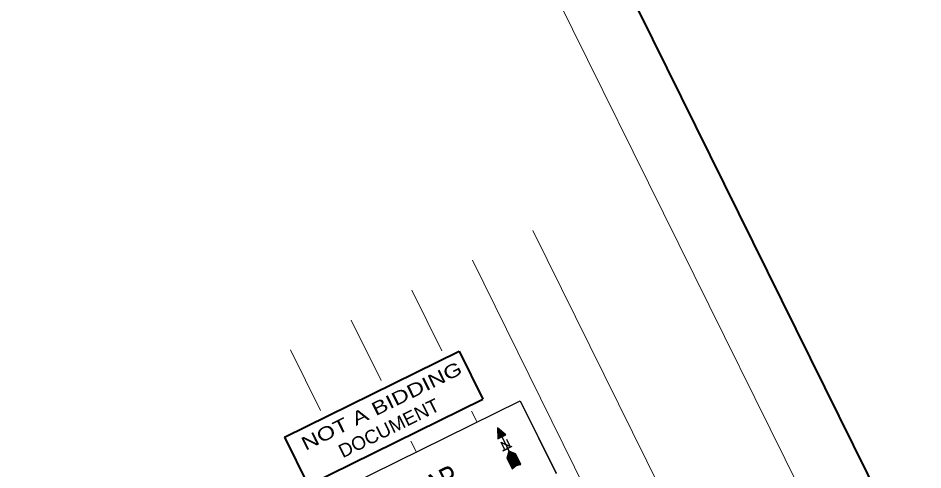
# Model space of a CAD drawing. Extents: x 2356606 to 2371222, y 6973096 to 6982644.
# Drawn here: x 2356606 to 2357945, y 6974009 to 6974679 of the extents above; entities that cross this region are included whole.
import ezdxf
from ezdxf.enums import TextEntityAlignment as Align

# ---------------------------------------------------------------- set-up
doc = ezdxf.new("R2010")
doc.units = 0
doc.header["$LTSCALE"] = 2
for name, color, linetype, lineweight in [('44', 7, 'Continuous', 13), ('62', 7, 'Continuous', 13), ('63', 7, 'Continuous', 13)]:
    doc.layers.add(name, color=color, linetype=linetype, lineweight=lineweight)

msp = doc.modelspace()

# ---------------------------------------------------------------- linework, layer by layer
at = {"layer": '44'}
msp.add_line((2358199.427, 6973096.266), (2356606.11, 6976324.656), dxfattribs=at)
at = {"layer": '44', "lineweight": 40}
msp.add_lwpolyline([(2358244.847, 6973230.201), (2356740.046, 6976279.238), (2369364.897, 6982510.022)], dxfattribs=at)
at = {"layer": '62'}
for p, q in [((2357367.886, 6974364.182), (2357723.359, 6973643.92)), ((2357278.212, 6974319.925), (2357633.685, 6973599.663)), ((2357277.056, 6974096.314), (2357285.076, 6974080.064)), ((2357315.643, 6974070.883), (2357316.066, 6974071.091)), ((2357321.745, 6974058.111), (2357315.651, 6974070.459)), ((2357315.66, 6974070.189), (2357316.587, 6974070.646)), ((2357315.665, 6974069.515), (2357317.118, 6974070.23)), ((2357321.182, 6974057.833), (2357315.684, 6974068.97)), ((2357315.692, 6974068.799), (2357317.65, 6974069.767)), ((2357315.698, 6974068.124), (2357318.16, 6974069.339)), ((2357315.734, 6974067.441), (2357318.682, 6974068.896)), ((2357320.613, 6974057.554), (2357315.734, 6974067.441)), ((2357315.761, 6974066.725), (2357319.211, 6974068.43)), ((2357320.048, 6974057.275), (2357315.767, 6974065.95)), ((2357315.768, 6974066.051), (2357319.722, 6974068.005)), ((2357315.783, 6974065.358), (2357320.265, 6974067.57)), ((2357315.8, 6974064.662), (2357320.785, 6974067.124)), ((2357319.484, 6974056.995), (2357315.809, 6974064.441)), ((2357315.817, 6974063.968), (2357321.326, 6974066.689)), ((2357315.853, 6974063.285), (2357321.847, 6974066.243)), ((2357318.919, 6974056.716), (2357315.861, 6974062.912)), ((2357315.87, 6974062.591), (2357322.388, 6974065.807)), ((2357315.887, 6974061.897), (2357322.909, 6974065.362)), ((2357318.354, 6974056.438), (2357315.894, 6974061.423)), ((2357315.92, 6974060.506), (2357323.951, 6974064.471)), ((2357315.922, 6974061.211), (2357323.43, 6974064.916)), ((2357315.937, 6974059.811), (2357324.471, 6974064.026)), ((2357317.79, 6974056.161), (2357315.946, 6974059.893)), ((2357315.974, 6974059.127), (2357325.013, 6974063.588)), ((2357317.224, 6974055.881), (2357315.981, 6974058.403)), ((2357315.988, 6974058.434), (2357325.534, 6974063.143)), ((2357315.997, 6974057.76), (2357326.046, 6974062.72)), ((2357322.31, 6974058.39), (2357316.017, 6974071.142)), ((2357316.042, 6974057.055), (2357326.596, 6974062.264)), ((2357316.06, 6974056.359), (2357327.117, 6974061.819)), ((2357316.067, 6974055.685), (2357327.629, 6974061.393)), ((2357322.874, 6974058.672), (2357317.219, 6974070.129)), ((2357323.42, 6974058.938), (2357318.401, 6974069.108)), ((2357324.005, 6974059.228), (2357319.613, 6974068.126)), ((2357324.57, 6974059.506), (2357320.815, 6974067.113)), ((2357325.114, 6974059.774), (2357321.988, 6974066.112)), ((2357325.7, 6974060.063), (2357323.211, 6974065.107)), ((2357326.245, 6974060.333), (2357324.392, 6974064.087)), ((2357326.81, 6974060.612), (2357325.585, 6974063.094)), ((2357327.394, 6974060.9), (2357326.807, 6974062.091)), ((2357187.382, 6974052.057), (2357195.402, 6974035.807)), ((2357316.659, 6974055.602), (2357316.034, 6974056.873)), ((2357316.113, 6974055.333), (2357316.083, 6974055.394)), ((2357329.561, 6974026.562), (2357342.335, 6974032.868)), ((2357329.586, 6974027.276), (2357341.772, 6974033.292)), ((2357329.8, 6974028.062), (2357340.997, 6974033.588)), ((2357329.839, 6974025.998), (2357342.614, 6974032.303)), ((2357330.035, 6974028.905), (2357340.226, 6974033.935)), ((2357330.118, 6974025.433), (2357342.891, 6974031.737)), ((2357330.26, 6974029.719), (2357339.443, 6974034.251)), ((2357330.517, 6974030.523), (2357338.671, 6974034.545)), ((2357330.732, 6974031.357), (2357337.898, 6974034.891)), ((2357339.716, 6974013.153), (2357330.732, 6974031.357)), ((2357330.97, 6974032.15), (2357337.122, 6974035.189)), ((2357340.211, 6974013.574), (2357330.988, 6974032.262)), ((2357331.194, 6974032.965), (2357336.339, 6974035.505)), ((2357340.706, 6974013.994), (2357331.245, 6974033.165)), ((2357331.43, 6974033.807), (2357335.567, 6974035.85)), ((2357341.204, 6974014.415), (2357331.501, 6974034.069)), ((2357331.667, 6974034.601), (2357334.794, 6974036.147)), ((2357341.696, 6974014.835), (2357331.755, 6974034.973)), ((2357331.891, 6974035.417), (2357334.031, 6974036.471)), ((2357342.206, 6974015.236), (2357332.017, 6974035.881)), ((2357332.119, 6974036.23), (2357333.248, 6974036.789)), ((2357342.699, 6974015.655), (2357332.272, 6974036.783)), ((2357343.273, 6974015.915), (2357332.896, 6974036.941)), ((2357343.898, 6974016.072), (2357333.781, 6974036.573)), ((2357344.504, 6974016.219), (2357334.644, 6974036.198)), ((2357345.16, 6974016.368), (2357335.537, 6974035.86)), ((2357345.774, 6974016.547), (2357336.421, 6974035.494)), ((2357346.388, 6974016.672), (2357337.274, 6974035.138)), ((2357347.03, 6974016.841), (2357338.178, 6974034.781)), ((2357347.637, 6974016.989), (2357339.042, 6974034.404)), ((2357348.261, 6974017.148), (2357339.925, 6974034.037)), ((2357348.906, 6974017.314), (2357340.829, 6974033.68)), ((2357349.51, 6974017.463), (2357341.682, 6974033.324)), ((2357337.231, 6974011.076), (2357329.451, 6974026.835)), ((2357337.745, 6974011.503), (2357329.727, 6974027.749)), ((2357338.222, 6974011.916), (2357329.964, 6974028.643)), ((2357338.716, 6974012.334), (2357330.218, 6974029.547)), ((2357330.398, 6974024.866), (2357343.171, 6974031.171)), ((2357339.211, 6974012.754), (2357330.477, 6974030.451)), ((2357330.677, 6974024.302), (2357343.45, 6974030.605)), ((2357330.956, 6974023.735), (2357343.731, 6974030.041)), ((2357331.235, 6974023.17), (2357344.008, 6974029.475)), ((2357331.514, 6974022.606), (2357344.287, 6974028.909)), ((2357331.791, 6974022.04), (2357344.566, 6974028.345)), ((2357332.07, 6974021.474), (2357344.843, 6974027.779)), ((2357332.352, 6974020.912), (2357345.124, 6974027.214)), ((2357332.621, 6974020.368), (2357345.393, 6974026.669)), ((2357332.908, 6974019.781), (2357345.683, 6974026.086)), ((2357333.187, 6974019.216), (2357345.96, 6974025.52)), ((2357333.458, 6974018.671), (2357346.23, 6974024.977)), ((2357333.744, 6974018.087), (2357346.517, 6974024.39)), ((2357334.013, 6974017.542), (2357346.788, 6974023.847)), ((2357334.293, 6974016.975), (2357347.065, 6974023.281)), ((2357334.581, 6974016.392), (2357347.354, 6974022.696)), ((2357334.849, 6974015.847), (2357347.622, 6974022.151)), ((2357335.129, 6974015.281), (2357347.901, 6974021.586)), ((2357335.409, 6974014.718), (2357348.181, 6974021.02)), ((2357335.686, 6974014.153), (2357348.461, 6974020.457)), ((2357335.965, 6974013.586), (2357348.738, 6974019.892)), ((2357336.244, 6974013.021), (2357349.016, 6974019.327)), ((2357343.766, 6974016.033), (2357349.295, 6974018.762)), ((2357346.649, 6974016.753), (2357349.577, 6974018.196)), ((2357336.52, 6974012.457), (2357342.254, 6974015.287)), ((2357336.802, 6974011.891), (2357340.211, 6974013.574)), ((2357337.082, 6974011.329), (2357338.169, 6974011.863)), ((2357349.489, 6974017.452), (2357349.854, 6974017.63))]:
    msp.add_line(p, q, dxfattribs=at)
at = {"layer": '62', "lineweight": 40}
for p, q in [((2357000.317, 6974057.993), (2357258.555, 6974185.442)), ((2357258.555, 6974185.442), (2357293.714, 6974114.204))]:
    msp.add_line(p, q, dxfattribs=at)
at = {"layer": '62', "lineweight": 25}
for p, q in [((2357315.488, 6974071.658), (2357343.151, 6974015.602)), ((2357323.572, 6974037.933), (2357336.973, 6974044.547))]:
    msp.add_line(p, q, dxfattribs=at)
at = {"layer": '62', "lineweight": 40}
msp.add_lwpolyline([(2357000.317, 6974057.993), (2357035.475, 6973986.756), (2357293.714, 6974114.204)], dxfattribs=at)
at = {"layer": '62', "lineweight": 25}
for points in [[(2356999.05, 6973805.301), (2356946.031, 6973912.733), (2357348.892, 6974111.56), (2357402.214, 6974004.278)], [(2357315.613, 6974071.396), (2357316.074, 6974055.313), (2357327.918, 6974061.159), (2357315.555, 6974071.517)], [(2357325.749, 6974040.388), (2357320.88, 6974050.254), (2357334.12, 6974044.069), (2357329.071, 6974054.299)], [(2357332.354, 6974037.024), (2357329.442, 6974026.804), (2357337.21, 6974011.065), (2357342.891, 6974015.826), (2357349.895, 6974017.552), (2357342.215, 6974033.108), (2357332.554, 6974037.074)]]:
    msp.add_lwpolyline(points, dxfattribs=at)
at = {"layer": '63'}
for p, q in [((2357188.539, 6974275.669), (2357232.797, 6974185.992)), ((2357098.865, 6974231.412), (2357143.123, 6974141.735)), ((2357009.192, 6974187.155), (2357053.45, 6974097.479)), ((2357277.056, 6974096.314), (2357285.076, 6974080.064)), ((2357315.513, 6974071.146), (2357315.936, 6974071.354)), ((2357321.615, 6974058.374), (2357315.521, 6974070.722)), ((2357315.53, 6974070.452), (2357316.457, 6974070.909)), ((2357315.535, 6974069.778), (2357316.988, 6974070.493)), ((2357321.052, 6974058.096), (2357315.554, 6974069.233)), ((2357315.562, 6974069.062), (2357317.52, 6974070.03)), ((2357315.568, 6974068.387), (2357318.03, 6974069.602)), ((2357315.604, 6974067.704), (2357318.552, 6974069.159)), ((2357320.483, 6974057.817), (2357315.604, 6974067.704)), ((2357315.631, 6974066.988), (2357319.081, 6974068.693)), ((2357319.918, 6974057.538), (2357315.637, 6974066.213)), ((2357315.638, 6974066.314), (2357319.592, 6974068.268)), ((2357315.653, 6974065.621), (2357320.135, 6974067.833)), ((2357315.67, 6974064.925), (2357320.655, 6974067.387)), ((2357319.354, 6974057.258), (2357315.679, 6974064.704)), ((2357315.687, 6974064.231), (2357321.196, 6974066.952)), ((2357315.723, 6974063.548), (2357321.717, 6974066.506)), ((2357318.789, 6974056.979), (2357315.731, 6974063.175)), ((2357315.74, 6974062.854), (2357322.258, 6974066.07)), ((2357315.757, 6974062.16), (2357322.779, 6974065.625)), ((2357318.224, 6974056.701), (2357315.764, 6974061.686)), ((2357315.79, 6974060.769), (2357323.821, 6974064.734)), ((2357315.792, 6974061.474), (2357323.3, 6974065.179)), ((2357315.807, 6974060.074), (2357324.341, 6974064.289)), ((2357317.66, 6974056.424), (2357315.816, 6974060.156)), ((2357315.844, 6974059.39), (2357324.883, 6974063.851)), ((2357317.094, 6974056.144), (2357315.851, 6974058.666)), ((2357315.858, 6974058.697), (2357325.404, 6974063.406)), ((2357315.867, 6974058.023), (2357325.916, 6974062.983)), ((2357322.18, 6974058.653), (2357315.887, 6974071.405)), ((2357315.912, 6974057.318), (2357326.466, 6974062.527)), ((2357315.93, 6974056.622), (2357326.987, 6974062.082)), ((2357315.937, 6974055.948), (2357327.499, 6974061.656)), ((2357322.744, 6974058.935), (2357317.089, 6974070.392)), ((2357323.29, 6974059.201), (2357318.271, 6974069.371)), ((2357323.875, 6974059.491), (2357319.483, 6974068.389)), ((2357324.44, 6974059.769), (2357320.685, 6974067.376)), ((2357324.984, 6974060.037), (2357321.858, 6974066.375)), ((2357325.57, 6974060.326), (2357323.081, 6974065.37)), ((2357326.115, 6974060.596), (2357324.262, 6974064.35)), ((2357326.68, 6974060.875), (2357325.455, 6974063.357)), ((2357327.264, 6974061.163), (2357326.677, 6974062.354)), ((2357187.382, 6974052.057), (2357195.402, 6974035.807)), ((2357316.529, 6974055.865), (2357315.904, 6974057.136)), ((2357315.983, 6974055.596), (2357315.953, 6974055.657)), ((2357329.431, 6974026.825), (2357342.205, 6974033.131)), ((2357329.456, 6974027.539), (2357341.642, 6974033.555)), ((2357329.67, 6974028.325), (2357340.867, 6974033.851)), ((2357329.709, 6974026.261), (2357342.484, 6974032.566)), ((2357329.905, 6974029.168), (2357340.096, 6974034.198)), ((2357329.988, 6974025.696), (2357342.761, 6974032)), ((2357330.13, 6974029.982), (2357339.313, 6974034.514)), ((2357330.268, 6974025.129), (2357343.041, 6974031.434)), ((2357330.387, 6974030.786), (2357338.541, 6974034.808)), ((2357330.602, 6974031.62), (2357337.768, 6974035.154)), ((2357339.586, 6974013.416), (2357330.602, 6974031.62)), ((2357330.84, 6974032.413), (2357336.992, 6974035.452)), ((2357340.081, 6974013.837), (2357330.858, 6974032.525)), ((2357331.064, 6974033.228), (2357336.209, 6974035.768)), ((2357340.576, 6974014.257), (2357331.115, 6974033.428)), ((2357331.3, 6974034.07), (2357335.437, 6974036.113)), ((2357341.074, 6974014.678), (2357331.371, 6974034.332)), ((2357331.537, 6974034.864), (2357334.664, 6974036.41)), ((2357341.566, 6974015.098), (2357331.625, 6974035.236)), ((2357331.761, 6974035.68), (2357333.901, 6974036.734)), ((2357342.076, 6974015.499), (2357331.887, 6974036.144)), ((2357331.989, 6974036.493), (2357333.118, 6974037.052)), ((2357342.569, 6974015.918), (2357332.142, 6974037.046)), ((2357343.143, 6974016.178), (2357332.766, 6974037.204)), ((2357343.768, 6974016.335), (2357333.651, 6974036.836)), ((2357344.374, 6974016.482), (2357334.514, 6974036.461)), ((2357345.03, 6974016.631), (2357335.407, 6974036.123)), ((2357345.644, 6974016.81), (2357336.291, 6974035.757)), ((2357346.258, 6974016.935), (2357337.144, 6974035.401)), ((2357346.9, 6974017.104), (2357338.048, 6974035.044)), ((2357347.507, 6974017.252), (2357338.912, 6974034.667)), ((2357348.131, 6974017.411), (2357339.795, 6974034.3)), ((2357348.776, 6974017.577), (2357340.699, 6974033.943)), ((2357349.38, 6974017.726), (2357341.552, 6974033.587)), ((2357337.101, 6974011.339), (2357329.321, 6974027.098)), ((2357337.615, 6974011.766), (2357329.597, 6974028.012)), ((2357338.092, 6974012.179), (2357329.834, 6974028.906)), ((2357338.586, 6974012.597), (2357330.088, 6974029.81)), ((2357339.081, 6974013.017), (2357330.347, 6974030.714)), ((2357330.547, 6974024.565), (2357343.32, 6974030.868)), ((2357330.826, 6974023.998), (2357343.601, 6974030.304)), ((2357331.105, 6974023.433), (2357343.878, 6974029.738)), ((2357331.384, 6974022.869), (2357344.157, 6974029.172)), ((2357331.661, 6974022.303), (2357344.436, 6974028.608)), ((2357331.94, 6974021.737), (2357344.713, 6974028.042)), ((2357332.222, 6974021.175), (2357344.994, 6974027.477)), ((2357332.491, 6974020.631), (2357345.263, 6974026.932)), ((2357332.778, 6974020.044), (2357345.553, 6974026.349)), ((2357333.057, 6974019.479), (2357345.83, 6974025.783)), ((2357333.328, 6974018.934), (2357346.1, 6974025.24)), ((2357333.614, 6974018.35), (2357346.387, 6974024.653)), ((2357333.883, 6974017.805), (2357346.658, 6974024.11)), ((2357334.163, 6974017.238), (2357346.935, 6974023.544)), ((2357334.451, 6974016.655), (2357347.224, 6974022.959)), ((2357334.719, 6974016.11), (2357347.492, 6974022.414)), ((2357334.999, 6974015.544), (2357347.771, 6974021.849)), ((2357335.279, 6974014.981), (2357348.051, 6974021.283)), ((2357335.556, 6974014.416), (2357348.331, 6974020.72)), ((2357335.835, 6974013.849), (2357348.608, 6974020.155)), ((2357336.114, 6974013.284), (2357348.886, 6974019.59)), ((2357343.636, 6974016.296), (2357349.165, 6974019.025)), ((2357346.519, 6974017.016), (2357349.447, 6974018.459)), ((2357336.39, 6974012.72), (2357342.124, 6974015.55)), ((2357336.672, 6974012.154), (2357340.081, 6974013.837)), ((2357336.952, 6974011.592), (2357338.039, 6974012.126)), ((2357349.359, 6974017.715), (2357349.724, 6974017.893))]:
    msp.add_line(p, q, dxfattribs=at)
at = {"layer": '63', "lineweight": 40}
for p, q in [((2357000.317, 6974057.993), (2357258.555, 6974185.442)), ((2357258.555, 6974185.442), (2357293.714, 6974114.204))]:
    msp.add_line(p, q, dxfattribs=at)
at = {"layer": '63', "lineweight": 25}
for p, q in [((2357315.358, 6974071.921), (2357343.021, 6974015.865)), ((2357323.442, 6974038.196), (2357336.843, 6974044.81))]:
    msp.add_line(p, q, dxfattribs=at)
for points in [[(2356998.92, 6973805.564), (2356945.901, 6973912.996), (2357348.762, 6974111.823), (2357402.084, 6974004.541)], [(2357315.483, 6974071.659), (2357315.944, 6974055.576), (2357327.788, 6974061.422), (2357315.425, 6974071.78)], [(2357325.619, 6974040.651), (2357320.75, 6974050.517), (2357333.99, 6974044.332), (2357328.941, 6974054.562)], [(2357332.224, 6974037.287), (2357329.312, 6974027.067), (2357337.08, 6974011.328), (2357342.761, 6974016.089), (2357349.765, 6974017.815), (2357342.085, 6974033.371), (2357332.424, 6974037.337)]]:
    msp.add_lwpolyline(points, dxfattribs=at)
at = {"layer": '63', "lineweight": 40}
msp.add_lwpolyline([(2357000.317, 6974057.993), (2357035.475, 6973986.756), (2357293.714, 6974114.204)], dxfattribs=at)

# ---------------------------------------------------------------- texts
at = {"layer": '62'}
for s, width, p in [('NOT A BIDDING', 1.3, (2357148.319, 6974095.277)), ('DOCUMENT', 1.05, (2357159.098, 6974062.455))]:
    msp.add_text(s, height=20, rotation=26.268, dxfattribs=dict(at, width=width)).set_placement(p, align=Align.CENTER)
at = {"layer": '62', "width": 0.85}
msp.add_text('VICINITY MAP', height=31.45, rotation=26.268, dxfattribs=at).set_placement((2357047.141, 6973884.294))
at = {"layer": '63'}
for s, width, p in [('NOT A BIDDING', 1.3, (2357148.319, 6974095.277)), ('DOCUMENT', 1.05, (2357159.098, 6974062.455))]:
    msp.add_text(s, height=20, rotation=26.268, dxfattribs=dict(at, width=width)).set_placement(p, align=Align.CENTER)
at = {"layer": '63', "width": 0.85}
msp.add_text('VICINITY MAP', height=31.45, rotation=26.268, dxfattribs=at).set_placement((2357047.011, 6973884.558))

doc.saveas('drawing.dxf')
